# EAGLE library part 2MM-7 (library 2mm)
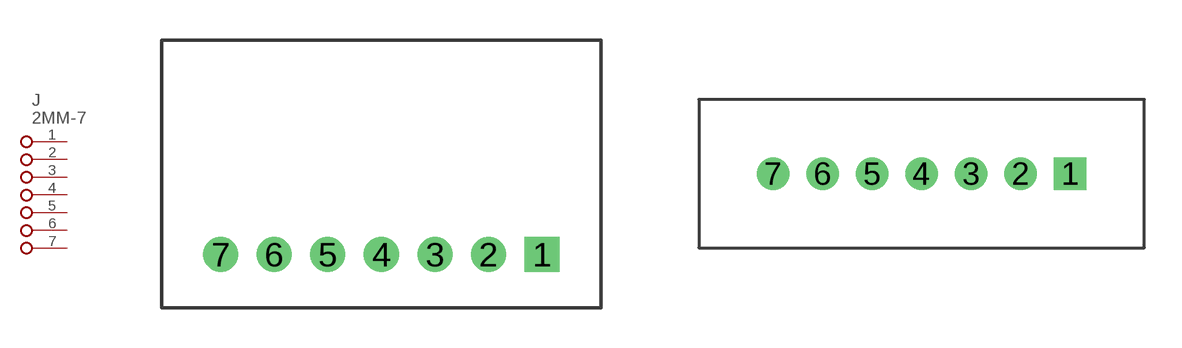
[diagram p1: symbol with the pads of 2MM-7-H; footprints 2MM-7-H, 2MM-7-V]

Designator prefix J

## 2MM-7H  [2MM-7-H]
1  1
2  2
3  3
4  4
5  5
6  6
7  7

## 2MM-7V  [2MM-7-V]
Pads as for 2MM-7-H

## Footprint 2MM-7-H (pad centres in mm)
drill 0.8 square: 1 0,0
drill 0.8 round: 2 -2,0; 3 -4,0; 4 -6,0; 5 -8,0; 6 -10,0; 7 -12,0

## Footprint 2MM-7-V (pad centres in mm)
drill 0.8 square: 1 0,0
drill 0.8 round: 2 -2,0; 3 -4,0; 4 -6,0; 5 -8,0; 6 -10,0; 7 -12,0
